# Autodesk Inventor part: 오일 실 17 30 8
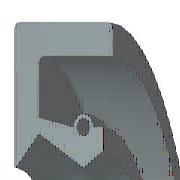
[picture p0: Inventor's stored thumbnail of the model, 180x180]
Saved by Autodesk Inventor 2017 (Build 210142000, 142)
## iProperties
IsCustomPart: 1
Created: 2012-02
Part Number: 오일 실 17 30 8
Material: 고무
Description: 오일-실
Document SubType Name: Modeling
Standard: KS B 2804
Designer: mduedu
Standards Organization: KS
Language: ko-KR
Size Designation: D - 17 30 8
Categories: <MemberInstance><Categories><Category DisplayName="샤프트 부품" InternalName="7f7aeb1f-a693-4053-b835-cee3144e0d98" Mnemonic="SHFT"><Category DisplayName="실링" Intern
Density: 0.93 g/cm^3
Appearance: 고무 - 검은색 - 버전 1.1
Author: mduedu
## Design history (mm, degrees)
revolve "본체" stored, may be unused: angle "d17" = 90 deg
revolve "스프링1" stored, may be unused: angle "d18" = 90 deg
body "Solid1"
sketch "스케치1"
  geometry: L1 (0, 15)-(8, 15); L2 (8, 13.25)-(1.75, 13.25); L3 (1.75, 10.25)-(4.9, 8.5); L4 (4.9, 8.5)-(0, 8.5); L5 (0, 0)-(9.586, 0) reference; L6 (4.9, 8.5)-(6.3, 9.375); L7 (0, 18)-(0, -3) reference; L8 (-1.941, 0)-(11.507, 0) reference; L9 (4.2, 10.6)-(1.75, 11.21); L10 (1.75, 11.21)-(1.75, 13.25); L11 (0, 15)-(0, 8.588); L12 (4.9, 8.5)-(0, 8.5); L13 (1.75, 10.25)-(0.152, 8.528); L14 (8, 15)-(8, 13.25); L15 (5.6, 10.6)-(6.3, 10.6); L16 (6.3, 10.6)-(6.3, 9.375); C1 r 0.455 at (4.9, 10.6); A1 r 0.7 centre (4.9, 10.6) between (5.6, 10.6) and (4.2, 10.6); A2 r 0.088 centre (0.088, 8.588) between (0, 8.588) and (0.152, 8.528); 1 further point
  constraints: 28 end point, 5 horizontal alignment, 5 point on line, 4 point on circle, 4 vertical alignment, 3 centre point, 3 tangent, 2 collinear, 2 horizontal, 2 perpendicular, 1 coincident, 1 parallel
  dimensions: "d0" = 30 diameter of L1 L5 (= SD2); "d1" = 1.75 distance of L1.end L2.start (= SD); "d2" = 0.91 diameter of C1 (= SPDI); "d3" = 1.4 diameter of A1 (= SPDA); "d4" = 17 diameter of L3.end L5 (= NND); "d5" = 20.5 diameter of L3.start L5 (= TKDM); "d7" = 22.42 diameter of L9.end L5 (= TKDM + 0.24 x SWDT); "d8" = 1.75 distance between parallel lines of L11 L10 (= SD); "d9" = 4.9 distance from line of L11 C1.centre (= SPDST); "d10" = 21.2 diameter of C1.centre L5 (= HLDM); "d11" = 0.0875 radius of A2 (= 0.25 x LAB); "d12" = 6.3 distance between parallel lines of L11 L16 (= SDI); "d13" = 18.75 diameter of L6.end L5 (= ABDM); "d14" = 8 distance from line of L11 L1.end (= SWDT)
fillet "모깎기1" dims "d6" = 0.3 (= RR)
other parameters: "SD2" = 30 [user parameter; used in 1 equation term], "SWDT" = 8 [user parameter; used in 2 equation terms], "RR" = 0.3 [user parameter; used in 1 equation term], "SD" = 1.75 [user parameter; used in 2 equation terms], "NND" = 17 [user parameter; used in 1 equation term], "SPDA" = 1.4 [user parameter; used in 1 equation term], "SPDI" = 0.91 [user parameter; used in 1 equation term], "TKDM" = 20.5 [user parameter; used in 2 equation terms], "HLDM" = 21.2 [user parameter; used in 1 equation term], "ABDM" = 18.75 [user parameter; used in 1 equation term], "SDI" = 6.3 [user parameter; used in 1 equation term], "SPDST" = 4.9 [user parameter; used in 1 equation term], "LAB" = 0.35 [user parameter; used in 1 equation term], "d15" = 0, "d16" = 0, "d19" = 0
